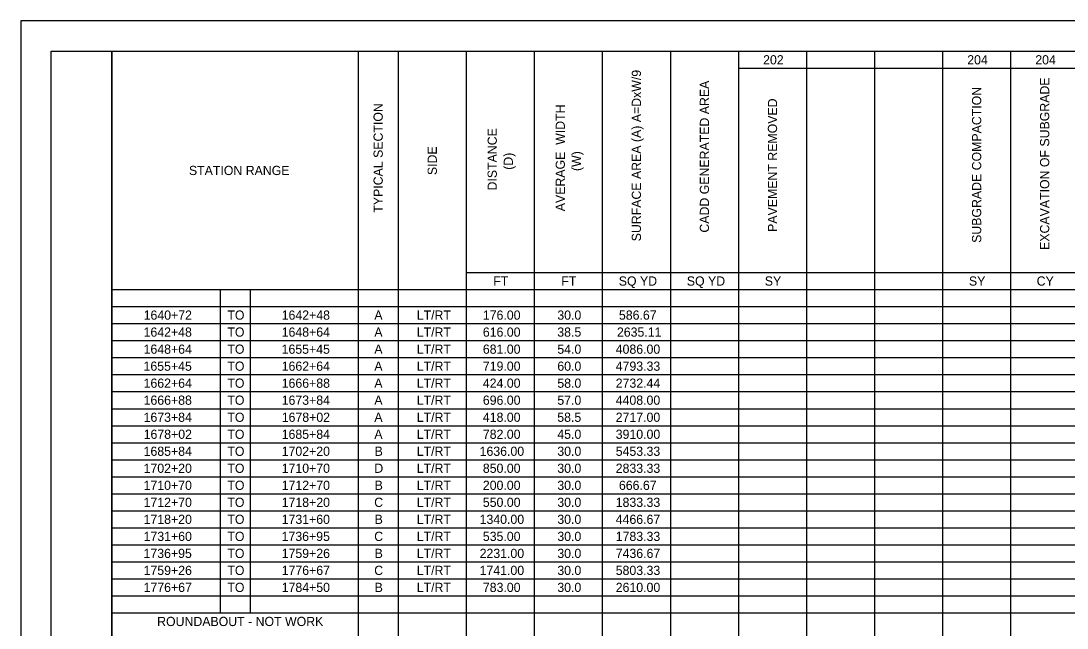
# Model space of a CAD drawing. Extents: x 0 to 34, y 0 to 22.
# Drawn here: x 0 to 17.23, y 12 to 22 of the extents above; entities that cross this region are included whole.
import ezdxf

# ---------------------------------------------------------------- set-up
doc = ezdxf.new("R2010")
doc.units = 0
for name, color, linetype in [('SH_Border', 7, 'Continuous'), ('SH_Cut_Line', 7, 'Continuous'), ('SH_Text', 7, 'Continuous')]:
    doc.layers.add(name, color=color, linetype=linetype)

msp = doc.modelspace()

# ---------------------------------------------------------------- linework, layer by layer
at = {"layer": 'SH_Border'}
for points in [[(0.5, 21.5), (1.5, 21.5), (1.5, 0.5), (0.5, 0.5)], [(1.5, 21.5), (33.5, 21.5), (33.5, 0.5), (1.5, 0.5)]]:
    msp.add_lwpolyline(points, close=True, dxfattribs=at)
at = {"layer": 'SH_Cut_Line'}
msp.add_lwpolyline([(0, 0), (34, 0), (34, 22), (0, 22)], close=True, dxfattribs=at)
at = {"layer": 'SH_Text'}
for p, q in [((1.5, 21.5), (32, 21.5)), ((1.5, 21.5), (1.5, 0.48)), ((5.556, 21.5), (5.556, 1.601)), ((6.215, 21.5), (6.215, 1.601)), ((7.336, 21.5), (7.336, 1.601)), ((8.457, 21.5), (8.457, 1.601)), ((9.578, 21.5), (9.578, 1.601)), ((10.699, 21.5), (10.699, 1.601)), ((11.821, 21.5), (11.821, 0.48)), ((12.942, 21.5), (12.942, 0.48)), ((14.063, 21.5), (14.063, 0.48)), ((15.184, 21.5), (15.184, 0.48)), ((16.305, 21.5), (16.305, 0.48)), ((11.821, 21.22), (32, 21.22)), ((7.336, 17.856), (32, 17.856)), ((1.5, 17.576), (32, 17.576)), ((3.281, 17.576), (3.281, 12.251)), ((3.775, 17.576), (3.775, 12.251)), ((1.5, 17.296), (32, 17.296)), ((1.5, 17.016), (32, 17.016)), ((1.5, 16.735), (32, 16.735)), ((1.5, 16.455), (32, 16.455)), ((1.5, 16.175), (32, 16.175)), ((1.5, 15.895), (32, 15.895)), ((1.5, 15.614), (32, 15.614)), ((1.5, 15.334), (32, 15.334)), ((1.5, 15.054), (32, 15.054)), ((1.5, 14.774), (32, 14.774)), ((1.5, 14.493), (32, 14.493)), ((1.5, 14.213), (32, 14.213)), ((1.5, 13.933), (32, 13.933)), ((1.5, 13.652), (32, 13.652)), ((1.5, 13.372), (32, 13.372)), ((1.5, 13.092), (32, 13.092)), ((1.5, 12.812), (32, 12.812)), ((1.5, 12.531), (32, 12.531)), ((1.5, 12.251), (32, 12.251))]:
    msp.add_line(p, q, dxfattribs=at)

# ---------------------------------------------------------------- texts
for s, height, p in [('202', 0.1517, (12.227, 21.284)), ('204', 0.1517, (15.59, 21.284)), ('204', 0.1517, (16.711, 21.284)), ('STATION RANGE', 0.15168, (2.768, 19.462)), ('FT', 0.1517, (7.782, 17.641)), ('FT', 0.1517, (8.903, 17.641)), ('SQ YD', 0.1517, (9.849, 17.641)), ('SQ YD', 0.1517, (10.97, 17.641)), ('SY', 0.1517, (12.255, 17.641)), ('SY', 0.1517, (15.618, 17.641)), ('CY', 0.1517, (16.734, 17.641)), ('LT/RT', 0.1517, (6.521, 17.08)), ('1640+72', 0.1517, (2.022, 17.08)), ('TO', 0.1517, (3.401, 17.08)), ('1642+48', 0.1517, (4.296, 17.08)), ('A', 0.152, (5.822, 17.08)), ('176.00', 0.1517, (7.61, 17.08)), ('30.0', 0.1517, (8.837, 17.08)), ('586.67', 0.1517, (9.852, 17.08)), ('1642+48', 0.1517, (2.021, 16.8)), ('TO', 0.1517, (3.401, 16.8)), ('1648+64', 0.1517, (4.296, 16.8)), ('A', 0.152, (5.822, 16.8)), ('LT/RT', 0.1517, (6.521, 16.8)), ('616.00', 0.1517, (7.61, 16.8)), ('38.5', 0.1517, (8.836, 16.8)), ('2635.11', 0.1517, (9.819, 16.8)), ('1648+64', 0.1517, (2.021, 16.519)), ('TO', 0.1517, (3.401, 16.519)), ('1655+45', 0.1517, (4.295, 16.519)), ('A', 0.152, (5.822, 16.519)), ('LT/RT', 0.1517, (6.521, 16.519)), ('681.00', 0.1517, (7.61, 16.519)), ('54.0', 0.1517, (8.837, 16.519)), ('4086.00', 0.1517, (9.799, 16.519)), ('1655+45', 0.1517, (2.02, 16.239)), ('TO', 0.1517, (3.401, 16.239)), ('1662+64', 0.1517, (4.296, 16.239)), ('A', 0.152, (5.822, 16.239)), ('LT/RT', 0.1517, (6.521, 16.239)), ('719.00', 0.1517, (7.61, 16.239)), ('60.0', 0.1517, (8.837, 16.239)), ('4793.33', 0.1517, (9.799, 16.239)), ('1662+64', 0.1517, (2.021, 15.959)), ('TO', 0.1517, (3.401, 15.959)), ('1666+88', 0.1517, (4.296, 15.959)), ('A', 0.152, (5.822, 15.959)), ('LT/RT', 0.1517, (6.521, 15.959)), ('424.00', 0.1517, (7.61, 15.959)), ('58.0', 0.1517, (8.837, 15.959)), ('2732.44', 0.1517, (9.799, 15.959)), ('1666+88', 0.1517, (2.021, 15.679)), ('TO', 0.1517, (3.401, 15.679)), ('1673+84', 0.1517, (4.296, 15.679)), ('A', 0.152, (5.822, 15.679)), ('LT/RT', 0.1517, (6.521, 15.679)), ('696.00', 0.1517, (7.61, 15.679)), ('57.0', 0.1517, (8.837, 15.679)), ('4408.00', 0.1517, (9.799, 15.679)), ('1673+84', 0.1517, (2.021, 15.398)), ('TO', 0.1517, (3.401, 15.398)), ('1678+02', 0.1517, (4.297, 15.398)), ('A', 0.152, (5.822, 15.398)), ('LT/RT', 0.1517, (6.521, 15.398)), ('418.00', 0.1517, (7.61, 15.398)), ('58.5', 0.1517, (8.836, 15.398)), ('2717.00', 0.1517, (9.799, 15.398)), ('1678+02', 0.1517, (2.022, 15.118)), ('TO', 0.1517, (3.401, 15.118)), ('1685+84', 0.1517, (4.296, 15.118)), ('A', 0.152, (5.822, 15.118)), ('LT/RT', 0.1517, (6.521, 15.118)), ('782.00', 0.1517, (7.61, 15.118)), ('45.0', 0.1517, (8.837, 15.118)), ('3910.00', 0.1517, (9.799, 15.118)), ('LT/RT', 0.1517, (6.521, 14.838)), ('1685+84', 0.1517, (2.021, 14.838)), ('TO', 0.1517, (3.401, 14.838)), ('1702+20', 0.1517, (4.296, 14.838)), ('B', 0.152, (5.827, 14.838)), ('1636.00', 0.1517, (7.557, 14.838)), ('30.0', 0.1517, (8.837, 14.838)), ('5453.33', 0.1517, (9.799, 14.838)), ('1702+20', 0.1517, (2.021, 14.558)), ('TO', 0.1517, (3.401, 14.558)), ('1710+70', 0.1517, (4.296, 14.558)), ('D', 0.152, (5.822, 14.558)), ('LT/RT', 0.1517, (6.521, 14.558)), ('850.00', 0.1517, (7.61, 14.558)), ('30.0', 0.1517, (8.837, 14.558)), ('2833.33', 0.1517, (9.799, 14.558)), ('1710+70', 0.1517, (2.021, 14.277)), ('TO', 0.1517, (3.401, 14.277)), ('1712+70', 0.1517, (4.296, 14.277)), ('B', 0.152, (5.827, 14.277)), ('LT/RT', 0.1517, (6.521, 14.277)), ('200.00', 0.1517, (7.61, 14.277)), ('30.0', 0.1517, (8.837, 14.277)), ('666.67', 0.1517, (9.852, 14.277)), ('1712+70', 0.1517, (2.021, 13.997)), ('TO', 0.1517, (3.401, 13.997)), ('1718+20', 0.1517, (4.296, 13.997)), ('C', 0.152, (5.82, 13.997)), ('LT/RT', 0.1517, (6.521, 13.997)), ('550.00', 0.1517, (7.61, 13.997)), ('30.0', 0.1517, (8.837, 13.997)), ('1833.33', 0.1517, (9.799, 13.997)), ('1718+20', 0.1517, (2.021, 13.717)), ('TO', 0.1517, (3.401, 13.717)), ('1731+60', 0.1517, (4.296, 13.717)), ('B', 0.152, (5.827, 13.717)), ('LT/RT', 0.1517, (6.521, 13.717)), ('1340.00', 0.1517, (7.557, 13.717)), ('30.0', 0.1517, (8.837, 13.717)), ('4466.67', 0.1517, (9.799, 13.717)), ('1731+60', 0.1517, (2.021, 13.436)), ('TO', 0.1517, (3.401, 13.436)), ('1736+95', 0.1517, (4.295, 13.436)), ('C', 0.152, (5.82, 13.436)), ('LT/RT', 0.1517, (6.521, 13.436)), ('535.00', 0.1517, (7.61, 13.436)), ('30.0', 0.1517, (8.837, 13.436)), ('1783.33', 0.1517, (9.799, 13.436)), ('1736+95', 0.1517, (2.02, 13.156)), ('TO', 0.1517, (3.401, 13.156)), ('1759+26', 0.1517, (4.296, 13.156)), ('B', 0.152, (5.827, 13.156)), ('LT/RT', 0.1517, (6.521, 13.156)), ('2231.00', 0.1517, (7.557, 13.156)), ('30.0', 0.1517, (8.837, 13.156)), ('7436.67', 0.1517, (9.799, 13.156)), ('1759+26', 0.1517, (2.021, 12.876)), ('TO', 0.1517, (3.401, 12.876)), ('1776+67', 0.1517, (4.296, 12.876)), ('C', 0.152, (5.82, 12.876)), ('LT/RT', 0.1517, (6.521, 12.876)), ('1741.00', 0.1517, (7.557, 12.876)), ('30.0', 0.1517, (8.837, 12.876)), ('5803.33', 0.1517, (9.799, 12.876)), ('LT/RT', 0.1517, (6.521, 12.596)), ('1776+67', 0.1517, (2.021, 12.596)), ('TO', 0.1517, (3.401, 12.596)), ('1784+50', 0.1517, (4.296, 12.596)), ('B', 0.152, (5.827, 12.596)), ('783.00', 0.1517, (7.61, 12.596)), ('30.0', 0.1517, (8.837, 12.596)), ('2610.00', 0.1517, (9.799, 12.596)), ('ROUNDABOUT - NOT WORK', 0.15168, (2.244, 12.035))]:
    msp.add_text(s, height=height, dxfattribs=at).set_placement(p)
for s, height, p in [('SURFACE AREA (A) A=DxW/9', 0.15168, (10.215, 18.371)), ('EXCAVATION OF SUBGRADE', 0.15168, (16.941, 18.229)), ('CADD GENERATED AREA', 0.15168, (11.336, 18.514)), ('SUBGRADE COMPACTION', 0.15168, (15.82, 18.345)), ('PAVEMENT REMOVED', 0.15168, (12.457, 18.526)), ('TYPICAL SECTION', 0.15168, (5.961, 18.842)), ('AVERAGE  WIDTH                                                                                       ', 0.151676, (8.961, 18.866)), ('DISTANCE                                                                                                        ', 0.151676, (7.84, 19.208)), ('SIDE', 0.1517, (6.852, 19.461)), ('(W)', 0.1517, (9.226, 19.528)), ('(D)', 0.1517, (8.105, 19.549))]:
    msp.add_text(s, height=height, rotation=90, dxfattribs=at).set_placement(p)

doc.saveas('drawing.dxf')
